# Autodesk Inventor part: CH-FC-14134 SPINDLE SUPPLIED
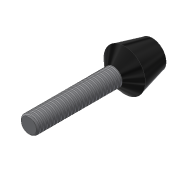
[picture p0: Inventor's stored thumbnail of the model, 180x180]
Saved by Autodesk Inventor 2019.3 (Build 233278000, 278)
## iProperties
Created: 2012-07
Part Number: CH-FC-14134 SPINDLE SUPPLIED
Material: Ogólny
Document SubType Name: Modeling
Designer: CADENGINEERING4
Density: 1 g/cm^3
Appearance: Domyślna
Author: CADENGINEERING4
Revision Number: ÈÎºÎ
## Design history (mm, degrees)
feature "NONE"
node "Bryła1"
